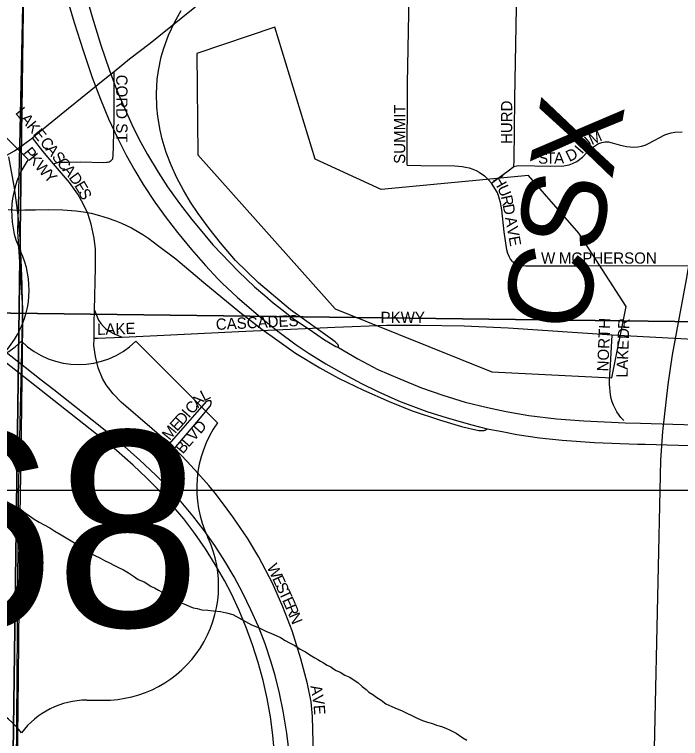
# Model space of a CAD drawing. Extents: x 0 to 68, y 0 to 52.9.
# Drawn here: x 43.122 to 43.713, y 37.042 to 37.686 of the extents above; entities that cross this region are included whole.
import ezdxf

# ---------------------------------------------------------------- set-up
doc = ezdxf.new("R2010")
doc.units = 0
for name, color, linetype in [('Default', 7, 'Continuous'), ('GM_X_Minor_Lake', 7, 'Continuous'), ('GM_X_Minor_River', 7, 'Continuous'), ('GM_X_State_Route', 7, 'Continuous'), ('GM_X_Township', 7, 'Continuous')]:
    doc.layers.add(name, color=color, linetype=linetype)

msp = doc.modelspace()

# ---------------------------------------------------------------- linework, layer by layer
at = {"layer": 'Default'}
for p, q in [((43.13372, 37.55711), (43.07571, 37.61512)), ((43.30182, 37.32304), (43.22931, 37.39555)), ((41.10506, 37.2633), (50.34506, 37.2633)), ((43.18581, 37.0765), (43.20031, 37.0765))]:
    msp.add_line(p, q, dxfattribs=at)
for points in [[(43.64162, 32.7683), (43.64334, 34.0176), (43.64455, 34.6783), (43.65599, 35.34849), (43.66788, 36.0083), (43.67702, 36.44587), (43.68602, 36.84543), (43.69035, 37.04683), (43.69592, 37.28989), (43.69757, 37.31546), (43.70235, 37.35703), (43.70606, 37.38349), (43.71865, 37.45038), (43.791, 37.87267), (43.79415, 37.89545), (43.79589, 37.91564), (43.79763, 37.93547), (43.7985, 37.95966), (43.79937, 37.99098), (43.80146, 38.12323), (43.80732, 38.54108), (43.80967, 38.71924)], [(43.47039, 37.55202), (43.47086, 37.62482), (43.4719, 37.68686), (43.47308, 37.74856), (43.47388, 37.77555), (43.47402, 37.81026), (43.47409, 37.83453), (43.47449, 37.84897)], [(43.21006, 37.63545), (43.22377, 37.6466), (43.24225, 37.66065), (43.24996, 37.66663), (43.33669, 37.73692), (43.36987, 37.76372), (43.38597, 37.77701)], [(43.56516, 37.5508), (43.56543, 37.5563), (43.56592, 37.58308), (43.56598, 37.61095), (43.56885, 37.7575)], [(43.4093, 37.38988), (43.40944, 37.39043), (43.40944, 37.39076), (43.40935, 37.39135), (43.40928, 37.39168), (43.4092, 37.39194), (43.40907, 37.39231), (43.40885, 37.39273), (43.40867, 37.39301), (43.40839, 37.3934), (43.40819, 37.39362), (43.40778, 37.39401), (43.40721, 37.39452), (43.40651, 37.39504), (43.40408, 37.39682), (43.39776, 37.40136), (43.36674, 37.42348), (43.33825, 37.44747), (43.31797, 37.46735), (43.30461, 37.48292), (43.29442, 37.49579), (43.28471, 37.50904), (43.27792, 37.51932), (43.27162, 37.52988), (43.26587, 37.54079), (43.26076, 37.55199), (43.2564, 37.56349), (43.2528, 37.57528), (43.25088, 37.58325), (43.24882, 37.59539), (43.24799, 37.60355), (43.24763, 37.61586), (43.24835, 37.62814), (43.24939, 37.63628), (43.25191, 37.64833), (43.2542, 37.65619), (43.25844, 37.66775), (43.26368, 37.67887), (43.26961, 37.68964)], [(43.13749, 37.57644), (43.14239, 37.58043), (43.16767, 37.60119), (43.20339, 37.63003), (43.21006, 37.63545)], [(43.15611, 37.55332), (43.15989, 37.55438), (43.162, 37.55469), (43.16355, 37.55478), (43.16858, 37.55483), (43.18005, 37.55494), (43.20108, 37.55455), (43.20341, 37.55467), (43.20436, 37.55483), (43.20579, 37.5552), (43.20672, 37.5557), (43.20753, 37.55626), (43.20843, 37.55713), (43.20883, 37.55768), (43.20908, 37.55855), (43.20926, 37.56004), (43.20945, 37.56916), (43.21005, 37.59377), (43.21029, 37.61121), (43.21022, 37.62794), (43.21006, 37.63545)], [(43.11058, 37.55851), (43.1215, 37.56476), (43.12951, 37.57034), (43.13749, 37.57644)], [(43.15611, 37.55332), (43.14686, 37.5646), (43.13749, 37.57644)], [(43.56516, 37.5508), (43.56775, 37.55139), (43.56957, 37.55168), (43.59762, 37.55135), (43.60949, 37.55141), (43.61249, 37.55197), (43.61438, 37.55253), (43.61739, 37.55353), (43.62106, 37.55531), (43.62607, 37.5591), (43.63029, 37.56354), (43.63513, 37.5678), (43.63769, 37.56968), (43.64041, 37.57123), (43.64329, 37.57233), (43.6463, 37.57287), (43.64934, 37.57277), (43.65241, 37.57208), (43.65868, 37.57021), (43.66516, 37.56877), (43.66848, 37.56835), (43.67185, 37.5682), (43.67522, 37.56836), (43.67857, 37.56893), (43.68179, 37.56997), (43.68485, 37.57135), (43.69927, 37.57896), (43.70212, 37.5801), (43.70506, 37.58093), (43.70817, 37.58137), (43.71464, 37.58174)], [(43.12769, 37.31323), (43.1277, 37.31436), (43.12904, 37.41053), (43.12856, 37.44613), (43.12765, 37.46804), (43.12635, 37.49124), (43.1248, 37.50719), (43.12427, 37.51217), (43.1217, 37.53188), (43.11654, 37.55949)], [(43.19258, 37.42307), (43.1937, 37.4612), (43.19343, 37.47751), (43.19238, 37.48713), (43.18961, 37.49977), (43.18663, 37.509), (43.18275, 37.51784), (43.17793, 37.52622), (43.17038, 37.53679), (43.15611, 37.55332)], [(43.47039, 37.55202), (43.48268, 37.55169), (43.51263, 37.55143), (43.51918, 37.55096), (43.52238, 37.55043), (43.52554, 37.54968), (43.52862, 37.54867), (43.53161, 37.54742), (43.53446, 37.54589), (43.53902, 37.54274), (43.5423, 37.53941), (43.54532, 37.53608)], [(43.54532, 37.53608), (43.55135, 37.54057), (43.56023, 37.54719), (43.56516, 37.5508)], [(43.5639, 37.4666), (43.56223, 37.46849), (43.56133, 37.47027), (43.55991, 37.47343), (43.55906, 37.47675), (43.55672, 37.49297), (43.55443, 37.51254), (43.55333, 37.51891), (43.55258, 37.52202), (43.5516, 37.52505), (43.55037, 37.52797), (43.54532, 37.53608)], [(43.11606, 37.51283), (43.12427, 37.51217)], [(43.12427, 37.51217), (43.13082, 37.51229), (43.14034, 37.51247), (43.15217, 37.51281), (43.16451, 37.5124), (43.17615, 37.51163), (43.18299, 37.51076), (43.1896, 37.50942), (43.1971, 37.50745), (43.20492, 37.50485), (43.21072, 37.50291), (43.21681, 37.50044), (43.22541, 37.49637), (43.23206, 37.49253), (43.23561, 37.49037), (43.24083, 37.48678), (43.24869, 37.48089), (43.26491, 37.46876), (43.28995, 37.44768), (43.32174, 37.42153), (43.34128, 37.40643), (43.35461, 37.39679), (43.3713, 37.38491), (43.39279, 37.37193), (43.40935, 37.36269), (43.43179, 37.35195), (43.45433, 37.34192), (43.47491, 37.3338), (43.50017, 37.32537), (43.51864, 37.31993), (43.52494, 37.31842), (43.53417, 37.31634), (43.53508, 37.31621), (43.53621, 37.3161), (43.5368, 37.3161), (43.53746, 37.31613), (43.53808, 37.3162), (43.53874, 37.31634), (43.53933, 37.3165), (43.53983, 37.31666), (43.54008, 37.31673), (43.54028, 37.31683), (43.54048, 37.31692), (43.54067, 37.31707), (43.5409, 37.31728), (43.54102, 37.31738), (43.54116, 37.31756), (43.54139, 37.31783)], [(43.5639, 37.4666), (43.56535, 37.46559), (43.56693, 37.46453), (43.5692, 37.46361), (43.57257, 37.46277), (43.57594, 37.46253), (43.62519, 37.4626), (43.74003, 37.46289)], [(43.19224, 37.39823), (43.19226, 37.41186), (43.19258, 37.42307)], [(43.19258, 37.42307), (43.19448, 37.41864), (43.19634, 37.41421), (43.19818, 37.41125), (43.20064, 37.40875), (43.20268, 37.40663), (43.20559, 37.40463), (43.21024, 37.40202), (43.21722, 37.3993)], [(43.35266, 37.02914), (43.35117, 37.04551), (43.349, 37.06181), (43.34616, 37.07801), (43.34258, 37.09407), (43.33818, 37.10992), (43.33312, 37.12556), (43.32746, 37.14101), (43.32119, 37.15621), (43.31424, 37.17112), (43.30815, 37.18278), (43.29997, 37.19705), (43.29123, 37.21099), (43.28192, 37.22454), (43.27199, 37.23765), (43.26147, 37.2503), (43.2504, 37.26246), (43.23884, 37.27416), (43.22688, 37.28543), (43.21208, 37.29846), (43.19434, 37.31308), (43.14536, 37.35166), (43.07056, 37.41047)], [(43.21722, 37.3993), (43.24828, 37.40062), (43.32064, 37.40415), (43.40604, 37.40822), (43.45204, 37.40977), (43.48161, 37.40994), (43.52105, 37.40929), (43.56016, 37.40749), (43.6526, 37.40131)], [(43.25928, 37.30439), (43.24391, 37.31784), (43.21635, 37.34152), (43.2093, 37.3487), (43.2031, 37.35673), (43.19966, 37.36259), (43.19583, 37.37204), (43.19344, 37.3819), (43.19222, 37.39192), (43.19224, 37.39823)], [(43.19224, 37.39823), (43.19554, 37.39837), (43.21722, 37.3993)], [(43.65032, 37.359), (43.65058, 37.36701), (43.65071, 37.36891), (43.6526, 37.40131)], [(43.6526, 37.40131), (43.72456, 37.39757), (43.764, 37.39574), (43.79033, 37.39515), (43.81995, 37.39527), (43.8583, 37.39597), (43.90519, 37.3974), (43.92343, 37.39778)], [(43.14535, 37.36108), (43.10372, 37.39358)], [(43.21959, 37.30172), (43.218, 37.30311), (43.19774, 37.3198), (43.15652, 37.35236), (43.14535, 37.36108)], [(43.66279, 37.32512), (43.66015, 37.32792), (43.65676, 37.3329), (43.65365, 37.33874), (43.65256, 37.34171), (43.65168, 37.34475), (43.65104, 37.34785), (43.65027, 37.35736), (43.65032, 37.359)], [(43.25928, 37.30439), (43.26324, 37.30893), (43.28382, 37.3325), (43.2926, 37.34224), (43.29293, 37.3425), (43.29333, 37.34273), (43.29369, 37.34286), (43.29406, 37.34296), (43.29441, 37.34302), (43.29491, 37.34304), (43.29583, 37.34279)], [(43.26363, 37.30058), (43.26669, 37.30392), (43.28525, 37.32571), (43.2952, 37.33746), (43.29558, 37.33807), (43.29583, 37.33856), (43.29616, 37.33936), (43.29634, 37.3402), (43.29639, 37.34061), (43.29641, 37.34103), (43.29636, 37.34157), (43.29628, 37.34195), (43.29583, 37.34279)], [(43.12688, 37.25918), (43.12769, 37.31323)], [(43.36621, 36.88513), (43.36762, 36.95233), (43.36776, 36.98515), (43.36723, 37.00809), (43.36596, 37.02771), (43.36358, 37.04721), (43.36036, 37.0666), (43.35705, 37.08265), (43.3531, 37.09855), (43.34946, 37.11113), (43.34422, 37.12664), (43.33831, 37.1419), (43.33167, 37.15688), (43.32444, 37.17158), (43.3167, 37.18601), (43.30835, 37.20011), (43.29947, 37.21387), (43.29003, 37.22726), (43.28005, 37.24025), (43.2696, 37.25286), (43.25861, 37.265), (43.24711, 37.27667), (43.23278, 37.29013), (43.21959, 37.30172)], [(43.26363, 37.30058), (43.25928, 37.30439)], [(43.35071, 37.18057), (43.33871, 37.20377), (43.32864, 37.22061), (43.3157, 37.23952), (43.30547, 37.25326), (43.29987, 37.2604), (43.2942, 37.26733), (43.28436, 37.27828), (43.27489, 37.28881), (43.26363, 37.30058)], [(43.12129, 36.74559), (43.12266, 36.85223), (43.12425, 37.01656), (43.12504, 37.09728), (43.12637, 37.22448), (43.12688, 37.25918)], [(43.38411, 36.89902), (43.38701, 37.03915), (43.38639, 37.06204), (43.38501, 37.075), (43.38194, 37.09103), (43.37611, 37.11319), (43.36819, 37.13816), (43.36008, 37.1596), (43.35074, 37.18051), (43.35071, 37.18057)]]:
    msp.add_lwpolyline(points, dxfattribs=at)
for points in [[(42.87499, 38.47751), (43.93627, 38.46518), (43.9204, 37.41034), (42.85875, 37.42389)], [(41.80876, 37.97561), (43.13273, 37.95279), (43.11555, 36.67874), (43.11455, 36.64024), (41.78766, 36.70713)], [(43.13273, 37.95279), (44.41032, 37.93957), (44.34414, 36.66665), (43.11555, 36.67874)], [(43.9204, 37.41034), (43.92065, 37.39833), (43.90273, 36.34073), (42.83718, 36.36115), (42.85875, 37.42389)]]:
    msp.add_lwpolyline(points, close=True, dxfattribs=at)
for centre, radius, start, end in [((43.20024, 37.51053), 0.08121, 144.99907, 205.45288), ((43.05341, 37.44109), 0.08121, 269.36174, 25.16808), ((43.07704, 37.44733), 0.07251, 225.573, 314.427), ((43.17855, 37.44733), 0.07251, 225.573, 314.427), ((43.38498, 37.26481), 0.10151, 144.99907, 205.45288), ((43.20144, 37.17801), 0.10151, 269.36174, 25.16808), ((43.06979, 37.00399), 0.07251, 36.8699, 90), ((43.18581, 37.00399), 0.07251, 90, 143.1301)]:
    msp.add_arc(centre, radius, start, end, dxfattribs=at)
at = {"layer": 'GM_X_Minor_Lake'}
for points in [[(43.3528, 37.67472), (43.28373, 37.65132), (43.28436, 37.5614), (43.40662, 37.42449), (43.54574, 37.36829), (43.6522, 37.36317)], [(43.3528, 37.67472), (43.28373, 37.65132), (43.28436, 37.5614), (43.40662, 37.42449), (43.54574, 37.36829), (43.6522, 37.36317), (43.66488, 37.42633), (43.62282, 37.49157), (43.5781, 37.54278), (43.44735, 37.53057), (43.38882, 37.5573), (43.3528, 37.67472)], [(43.6522, 37.36317), (43.66488, 37.42633), (43.62282, 37.49157), (43.5781, 37.54278), (43.44735, 37.53057), (43.38882, 37.5573), (43.3528, 37.67472)]]:
    msp.add_lwpolyline(points, dxfattribs=at)
at = {"layer": 'GM_X_Minor_River'}
msp.add_lwpolyline([(43.09753, 37.26192), (43.12652, 37.24655), (43.13101, 37.24299), (43.135, 37.24043), (43.13899, 37.23738), (43.14349, 37.23482), (43.14798, 37.23226), (43.15298, 37.2297), (43.15748, 37.22664), (43.16297, 37.22357), (43.16897, 37.21999), (43.17496, 37.21641), (43.18245, 37.21181), (43.18794, 37.20773), (43.19294, 37.20517), (43.19744, 37.20311), (43.20143, 37.20056), (43.20594, 37.1985), (43.20994, 37.19645), (43.21393, 37.1944), (43.21844, 37.19235), (43.22293, 37.18979), (43.22743, 37.18673), (43.23142, 37.18367), (43.23692, 37.1816), (43.23992, 37.17957), (43.24291, 37.17752), (43.24591, 37.17649), (43.24941, 37.17444), (43.25291, 37.1724), (43.25691, 37.17035), (43.2609, 37.16779), (43.2649, 37.16524), (43.2689, 37.16319), (43.2719, 37.16215), (43.27691, 37.16009), (43.28041, 37.15855), (43.28392, 37.15801), (43.28793, 37.15696), (43.29345, 37.1564), (43.29847, 37.15585), (43.30449, 37.15528), (43.31001, 37.15422), (43.31552, 37.15266), (43.33201, 37.14344), (43.33902, 37.14086), (43.34502, 37.13778), (43.35002, 37.13572), (43.35452, 37.13367), (43.35802, 37.13212), (43.36202, 37.12957), (43.36602, 37.12752), (43.37052, 37.12496), (43.37551, 37.12189), (43.38001, 37.11933), (43.384, 37.11678), (43.3885, 37.11422), (43.39099, 37.11269), (43.39349, 37.11116), (43.39599, 37.10963), (43.39949, 37.10758), (43.40248, 37.10604), (43.40498, 37.10451), (43.40748, 37.10298), (43.41098, 37.10143), (43.41498, 37.09888), (43.41948, 37.09682), (43.42347, 37.09427), (43.42647, 37.09223), (43.43045, 37.08867), (43.43394, 37.08612), (43.43643, 37.08358), (43.43993, 37.08154), (43.44342, 37.07899), (43.44741, 37.07644), (43.4514, 37.07338), (43.4569, 37.07081), (43.46141, 37.06876), (43.46541, 37.06721), (43.47941, 37.06053), (43.48391, 37.05848), (43.48842, 37.05692), (43.49293, 37.05587), (43.49644, 37.05433), (43.49894, 37.0538), (43.50195, 37.05277), (43.50545, 37.05122), (43.50795, 37.05019), (43.51095, 37.04865), (43.51395, 37.04711), (43.51694, 37.04507), (43.51994, 37.04303), (43.52343, 37.04099)], dxfattribs=at)
at = {"layer": 'GM_X_State_Route'}
for points in [[(43.16934, 37.75816), (43.19055, 37.684), (43.19817, 37.65884), (43.20556, 37.63705), (43.21231, 37.61938), (43.21861, 37.60419), (43.22709, 37.58546), (43.23385, 37.57228), (43.2398, 37.56148), (43.24915, 37.54597), (43.25767, 37.53288), (43.26812, 37.5181), (43.27915, 37.50374), (43.29063, 37.48977), (43.2978, 37.48133), (43.32048, 37.45757), (43.33494, 37.44407), (43.34402, 37.43621), (43.35142, 37.42978), (43.36016, 37.42289), (43.36935, 37.41563), (43.38333, 37.40618), (43.397, 37.39692), (43.40693, 37.39105), (43.4093, 37.38988), (43.42656, 37.37991), (43.44438, 37.37059), (43.46394, 37.36203), (43.48308, 37.35425), (43.50223, 37.34758), (43.52208, 37.34151), (43.54172, 37.33673), (43.55827, 37.33305), (43.57851, 37.32957), (43.60305, 37.32649), (43.62737, 37.32481), (43.66417, 37.32303), (43.67783, 37.32266), (43.86049, 37.31703)], [(43.16849, 37.70023), (43.17463, 37.67898), (43.18248, 37.65397), (43.19066, 37.62995), (43.19791, 37.61081), (43.20514, 37.59343), (43.213, 37.57634), (43.22082, 37.56105), (43.22842, 37.5475), (43.23605, 37.53493), (43.24641, 37.51922), (43.25643, 37.50527), (43.26638, 37.49228), (43.27878, 37.47704), (43.29117, 37.46289), (43.30237, 37.45097), (43.30607, 37.44725), (43.31968, 37.43448), (43.34207, 37.41518), (43.35546, 37.40446), (43.37171, 37.39224), (43.38333, 37.38459), (43.39808, 37.37555), (43.41445, 37.36641), (43.42992, 37.35816), (43.44375, 37.35122), (43.45669, 37.34526), (43.46414, 37.3421), (43.48795, 37.33321), (43.50602, 37.32747), (43.52783, 37.3212), (43.54139, 37.31783), (43.55479, 37.3152), (43.56772, 37.3127), (43.58794, 37.30966), (43.60827, 37.30751), (43.63686, 37.30563), (43.67519, 37.30421)], [(43.67519, 37.30421), (43.6819, 37.30396), (43.8786, 37.29812), (44.06297, 37.29264), (44.2064, 37.28832), (44.48097, 37.28067), (44.71457, 37.27378), (44.78831, 37.27138), (44.88259, 37.269), (45.2473, 37.25834), (45.44401, 37.2525), (45.57514, 37.24871), (45.72414, 37.24408), (45.83581, 37.24067)]]:
    msp.add_lwpolyline(points, dxfattribs=at)
at = {"layer": 'GM_X_Township'}
msp.add_lwpolyline([(43.06441, 32.7683), (43.08393, 33.99592), (43.08445, 34.02868), (43.09249, 34.65268), (43.09292, 34.68642), (43.10458, 35.31419), (43.1053, 35.34562), (43.1113, 36.01383), (43.1191, 36.64269), (43.12347, 37.01757), (43.12518, 37.25841), (43.12908, 37.42523), (43.12464, 37.49311), (43.12504, 37.51468), (43.13199, 37.8314), (43.13205, 37.85841), (43.13228, 37.95106), (43.31455, 37.9477), (43.3203, 37.94792), (44.12143, 37.94309), (44.77759, 37.93161), (45.76356, 37.9078)], dxfattribs=at)

# ---------------------------------------------------------------- texts
at = {"layer": 'Default'}
for s, height, rotation, p in [('CORD ST', 0.01, 270, (43.21198, 37.6325)), ('HURD', 0.01, 90, (43.56374, 37.5709)), ('CSX', 0.07475, 80.02237, (43.62834, 37.40146)), ('L', 0.01, 309.54319, (43.1218, 37.59849)), ('SUMMIT', 0.01, 90, (43.46869, 37.5533)), ('A', 0.01, 309.53696, (43.12628, 37.59306)), ('K', 0.01, 309.5352, (43.13188, 37.58627)), ('E', 0.01, 309.54319, (43.13748, 37.57949)), ('M', 0.01, 24.14554, (43.63439, 37.56978)), ('C', 0.01, 309.54971, (43.14365, 37.57201)), ('U', 0.01, 40.51358, (43.62834, 37.56447)), ('A', 0.01, 309.55109, (43.14869, 37.56591)), ('I', 0.01, 49.49343, (43.62577, 37.56141)), ('P', 0.01, 309.29134, (43.12886, 37.56307)), ('K', 0.01, 309.54331, (43.13335, 37.55759)), ('S', 0.01, 309.5258, (43.1543, 37.55912)), ('S', 0.01, 0.16394, (43.58674, 37.55342)), ('T', 0.01, 0.18377, (43.59379, 37.55345)), ('A', 0.01, 1.31127, (43.60104, 37.55347)), ('D', 0.01, 26.43398, (43.61445, 37.55481)), ('W', 0.01, 310.9939, (43.13913, 37.5506)), ('C', 0.01, 309.54971, (43.15878, 37.55369)), ('A', 0.01, 309.53696, (43.16382, 37.54758)), ('Y', 0.01, 313.90518, (43.147, 37.54156)), ('D', 0.01, 306.49828, (43.16934, 37.5409)), ('E', 0.01, 301.15116, (43.17444, 37.53404)), ('H', 0.01, 299.55781, (43.54611, 37.53932)), ('S', 0.01, 296.41843, (43.17797, 37.5282)), ('U', 0.01, 292.79974, (43.55031, 37.53195)), ('R', 0.01, 282.13377, (43.55357, 37.5243)), ('D', 0.01, 280.57267, (43.55522, 37.51663)), ('A', 0.01, 280.41863, (43.55731, 37.50539)), ('V', 0.01, 280.39675, (43.55891, 37.49673)), ('E', 0.01, 280.42294, (43.56049, 37.48808)), ('W', 0.01, 0.00001, (43.58938, 37.46454)), ('MCPHERSON', 0.01, 0.00001, (43.60522, 37.46454)), ('PKWY', 0.01, 0.00001, (43.44682, 37.41174)), ('CASCADES', 0.01, 2.75597, (43.30067, 37.40558)), ('NORTH', 0.01, 87.66396, (43.6491, 37.36858)), ('R', 0.01, 87.87846, (43.66771, 37.40622)), ('LAKE', 0.01, 1.54736, (43.19509, 37.40118)), ('D', 0.01, 87.8797, (43.66738, 37.39743)), ('E', 0.01, 87.89608, (43.66702, 37.38775)), ('K', 0.01, 87.90154, (43.6667, 37.37896)), ('A', 0.01, 88.20735, (43.66643, 37.37018)), ('L', 0.01, 88.96184, (43.6663, 37.36317)), ('L', 0.01, 27.23693, (43.28991, 37.34191)), ('A', 0.01, 48.15411, (43.2848, 37.33594)), ('C', 0.01, 48.17864, (43.27952, 37.33004)), ('D', 0.01, 48.15411, (43.2707, 37.3202)), ('I', 0.01, 48.16943, (43.27658, 37.32676)), ('E', 0.01, 48.3256, (43.26603, 37.31495)), ('M', 0.01, 50.74006, (43.25942, 37.30686)), ('V', 0.01, 48.20126, (43.28086, 37.30604)), ('D', 0.01, 48.18497, (43.28673, 37.3126)), ('B', 0.01, 49.9333, (43.27116, 37.29476)), ('L', 0.01, 48.59561, (43.27622, 37.30077)), ('W', 0.01, 294.75284, (43.34556, 37.19505)), ('E', 0.01, 294.79561, (43.35036, 37.18465)), ('S', 0.01, 294.75606, (43.35331, 37.17826)), ('T', 0.01, 294.75604, (43.35626, 37.17187)), ('E', 0.01, 293.91256, (43.35919, 37.16551)), ('R', 0.01, 292.5545, (43.36202, 37.15914)), ('N', 0.01, 292.23984, (43.36505, 37.15183)), ('A', 0.01, 280.46124, (43.38443, 37.08901)), ('V', 0.01, 278.22595, (43.38601, 37.08046)), ('E', 0.01, 274.45738, (43.38725, 37.07193))]:
    msp.add_text(s, height=height, rotation=rotation, dxfattribs=at).set_placement(p)
msp.add_text('68', height=0.174024, dxfattribs=at).set_placement((43.02819, 37.14176))

doc.saveas('drawing.dxf')
